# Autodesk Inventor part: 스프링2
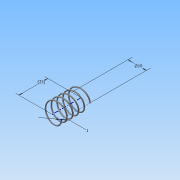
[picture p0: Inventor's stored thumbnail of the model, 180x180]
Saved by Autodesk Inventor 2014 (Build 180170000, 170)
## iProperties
Created: 2015-06
Part Number: 스프링2
Material: Generic
Document SubType Name: Modeling
Designer: Administrator
Density: 1 g/cm^3
Appearance: Default
Author: Administrator
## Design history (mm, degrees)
sketch "스케치1"
  geometry: L1 (0, 0)-(8, 0); L2 (8, 0)-(8, 14.5); L3 (8, 14.5)-(0, 14.5); L4 (0, 14.5)-(0, 0); C1 r 0.5 at (8, 0)
  constraints: 8 end point, 2 parallel, 1 centre point, 1 coincident, 1 horizontal, 1 perpendicular
  dimensions: "d0" = 14.5 distance of L3.end L1.start (derived); "d1" = 16 diameter of L2 L4; "d2" = 1 diameter of C1
feature "코일1" sketch "스케치1" pitch "d3" = 10; turns "d5" = 5; dims "d4" = 14.5 (= d0), "d6" = 0, angle "d7" = 90 deg, angle "d8" = 90 deg, "d9" = 0, "d10" = 0
sketch "스케치2"
  geometry: L1 (-8.5, 0)-(-7.5, 0) reference; 1 further point
  constraints: 1 horizontal alignment
extrude "돌출1" cut sketch "스케치2" stored distance "d11" = 10; taper "d12" = 0 deg
node "작업 평면1"
sketch "스케치3"
  geometry: L1 (-7.5, 0)-(-8.5, 0) reference; 1 further point
  constraints: 1 horizontal alignment
extrude "돌출2" cut sketch "스케치3" stored distance "d14" = 10; taper "d15" = 0 deg
node "솔리드1"
node "절단 모서리 투영1"
node "절단 모서리 투영2"
other parameters: "d13" = 14.5 (= d0)
